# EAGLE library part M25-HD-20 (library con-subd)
HD-20 Front Metal-Shell Right-Angle Posted Connectors 318 Mount 5747846-6 Source: http://catalog.tycoelectronics.com/TE/bin/TE.Connect?C=1&M=BYPN&TCPN=5747846-6&RQPN=5747846-6
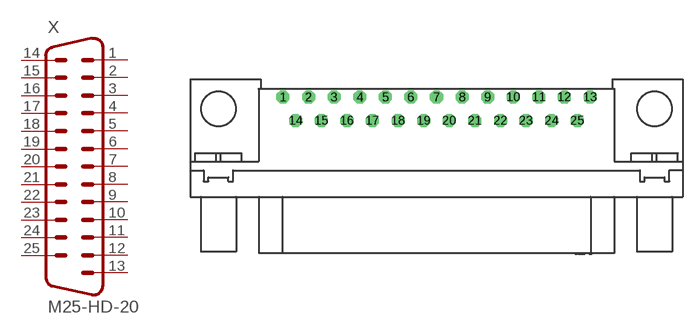
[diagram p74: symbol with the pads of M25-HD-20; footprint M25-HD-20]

Designator prefix X

## M25-HD-20 (OC_FARNELL: unknown; OC_NEWARK: unknown)  [M25-HD-20]
1  1  pas
2  2  pas
3  3  pas
4  4  pas
5  5  pas
6  6  pas
7  7  pas
8  8  pas
9  9  pas
10  10  pas
11  11  pas
12  12  pas
13  13  pas
14  14  pas
15  15  pas
16  16  pas
17  17  pas
18  18  pas
19  19  pas
20  20  pas
21  21  pas
22  22  pas
23  23  pas
24  24  pas
25  25  pas

## Footprint M25-HD-20 (pad centres in mm)
HD-20 Front Metal-Shell Right-Angle Posted Connectors 318 Mount 5747846-6 Source: http://catalog.tycoelectronics.com/TE/bin/TE.Connect?C=1&M=BYPN&TCPN=5747846-6&RQPN=5747846-6
drill 0.9 pad 1.3 octagon: 1 -16.561,1.27; 2 -13.792,1.27; 3 -11.049,1.27; 4 -8.28,1.27; 5 -5.512,1.27; 6 -2.769,1.27; 7 0,1.27; 8 2.769,1.27; 9 5.512,1.27; 10 8.28,1.27; 11 11.049,1.27; 12 13.792,1.27; 13 16.561,1.27; 14 -15.189,-1.27; 15 -12.421,-1.27; 16 -9.652,-1.27; 17 -6.909,-1.27; 18 -4.14,-1.27; 19 -1.372,-1.27; 20 1.372,-1.27; 21 4.14,-1.27; 22 6.909,-1.27; 23 9.652,-1.27; 24 12.421,-1.27; 25 15.189,-1.27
